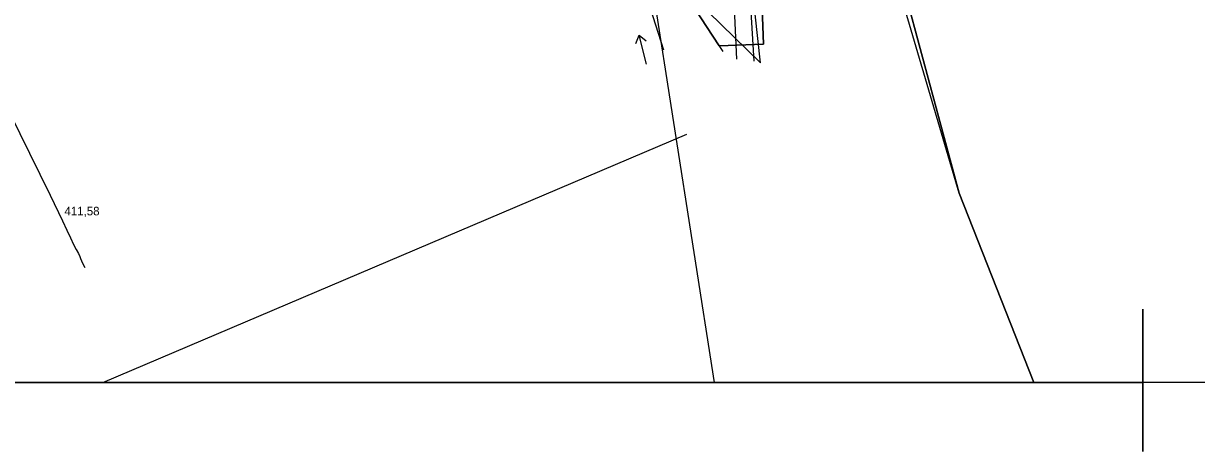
# Model space of a CAD drawing. Extents: x -574342 to -508101, y -1143544 to -1123894.
# Drawn here: x -508449.7 to -508312.9, y -1143544.1 to -1143494.2 of the extents above; entities that cross this region are included whole.
import ezdxf

# ---------------------------------------------------------------- set-up
doc = ezdxf.new("R2010")
doc.units = 0
for name, color, linetype in [('01_PARCELY_NAVRH_PC', 7, 'Continuous'), ('01_PARCELY_NAVRH_ZPF', 7, 'Continuous'), ('01_PARCELY_NAVRH_ŽP', 7, 'Continuous'), ('05_VHO_V_TOK_STAV', 7, 'Continuous'), ('37', 7, 'Continuous'), ('42', 7, 'Continuous'), ('43', 7, 'Continuous'), ('55', 7, 'Continuous'), ('60', 7, 'Continuous'), ('Level 1', 7, 'Continuous'), ('Level 255', 7, 'Continuous'), ('VRST VEDL', 7, 'Continuous')]:
    doc.layers.add(name, color=color, linetype=linetype)

msp = doc.modelspace()

# ---------------------------------------------------------------- linework, layer by layer
msp.add_lwpolyline([(-508319.1, -1143527.49), (-508319.1, -1143527.49), (-508319.1, -1143544.11), (-508319.1, -1143544.11)], close=True)
msp.add_lwpolyline([(-508319.1, -1143527.49), (-508319.1, -1143527.49), (-508319.1, -1143544.11), (-508319.1, -1143544.11)], close=True)
msp.add_lwpolyline([(-508319.1, -1143527.49), (-508319.1, -1143527.49), (-508319.1, -1143544.11), (-508319.1, -1143544.11)], close=True)
msp.add_lwpolyline([(-508319.1, -1143527.49), (-508319.1, -1143527.49), (-508319.1, -1143544.11), (-508319.1, -1143544.11)], close=True)
msp.add_lwpolyline([(-508319.1, -1143527.49), (-508319.1, -1143527.49), (-508319.1, -1143544.11), (-508319.1, -1143544.11)], close=True)
msp.add_lwpolyline([(-508319.1, -1143527.49), (-508319.1, -1143527.49), (-508319.1, -1143544.11), (-508319.1, -1143544.11)], close=True)
msp.add_lwpolyline([(-508319.1, -1143527.49), (-508319.1, -1143527.49), (-508319.1, -1143544.11), (-508319.1, -1143544.11)], close=True)
msp.add_lwpolyline([(-508319.1, -1143527.49), (-508319.1, -1143527.49), (-508319.1, -1143544.11), (-508319.1, -1143544.11)], close=True)
msp.add_lwpolyline([(-508319.1, -1143527.49), (-508319.1, -1143527.49), (-508319.1, -1143544.11), (-508319.1, -1143544.11)], close=True)
msp.add_lwpolyline([(-508319.1, -1143527.49), (-508319.1, -1143527.49), (-508319.1, -1143544.11), (-508319.1, -1143544.11)], close=True)
msp.add_lwpolyline([(-508319.1, -1143527.49), (-508319.1, -1143527.49), (-508319.1, -1143544.11), (-508319.1, -1143544.11)], close=True)
msp.add_lwpolyline([(-508319.1, -1143527.49), (-508319.1, -1143527.49), (-508319.1, -1143544.11), (-508319.1, -1143544.11)], close=True)
msp.add_lwpolyline([(-508319.1, -1143527.49), (-508319.1, -1143527.49), (-508319.1, -1143544.11), (-508319.1, -1143544.11)], close=True)
msp.add_lwpolyline([(-508319.1, -1143527.49), (-508319.1, -1143527.49), (-508319.1, -1143544.11), (-508319.1, -1143544.11)], close=True)
msp.add_lwpolyline([(-508319.1, -1143527.49), (-508319.1, -1143527.49), (-508319.1, -1143544.11), (-508319.1, -1143544.11)], close=True)
at = {"layer": '01_PARCELY_NAVRH_PC'}
msp.add_lwpolyline([(-508332.96, -1143441.42), (-508338.77, -1143439.04), (-508349.31, -1143439.84), (-508360.62, -1143444.62), (-508364.09, -1143448.52), (-508366.9, -1143457.4), (-508369.07, -1143476.28), (-508375.66, -1143485.8), (-508368.53, -1143496.78), (-508363.35, -1143496.57), (-508364.08, -1143476.62), (-508363.77, -1143471.67), (-508362.84, -1143461.25), (-508358.61, -1143451.78), (-508349.41, -1143446.37), (-508339.29, -1143444.12)], close=True, dxfattribs=at)
at = {"layer": '01_PARCELY_NAVRH_ZPF'}
for points in [[(-508319.1, -1143454.32), (-508332.96, -1143441.42), (-508339.29, -1143444.12), (-508349.41, -1143446.37), (-508358.61, -1143451.78), (-508355.5, -1143458.4), (-508340.54, -1143513.97), (-508331.83, -1143536.06)], [(-508331.83, -1143536.06), (-508319.1, -1143536.06)]]:
    msp.add_lwpolyline(points, dxfattribs=at)
at = {"layer": '01_PARCELY_NAVRH_ŽP'}
msp.add_line((-508488.49, -1143536.06), (-508331.83, -1143536.06), dxfattribs=at)
msp.add_lwpolyline([(-508331.83, -1143536.06), (-508340.54, -1143513.97), (-508355.5, -1143458.4), (-508358.61, -1143451.78), (-508362.84, -1143461.25), (-508363.77, -1143471.67), (-508364.08, -1143476.62), (-508363.35, -1143496.57), (-508368.53, -1143496.78), (-508375.66, -1143485.8), (-508391.38, -1143484.87), (-508409.7, -1143432.51), (-508425.23, -1143400.39), (-508448.26, -1143343.08)], dxfattribs=at)
at = {"layer": '05_VHO_V_TOK_STAV'}
for points in [[(-508369.06, -1143536.06), (-508378.54, -1143475.37), (-508396.74, -1143399.68), (-508414.31, -1143332.66)], [(-508440.39, -1143536.06), (-508372.3, -1143507.1)]]:
    msp.add_lwpolyline(points, dxfattribs=at)
at = {"layer": '37'}
msp.add_lwpolyline([(-508374.96, -1143497.27), (-508378.04, -1143487.63), (-508379.64, -1143474.59)], dxfattribs=at)
msp.add_lwpolyline([(-508374.96, -1143497.27), (-508378.04, -1143487.63), (-508379.64, -1143474.59)], dxfattribs=at)
at = {"layer": '42'}
for points in [[(-508369.8, -1143492.82), (-508363.69, -1143498.77), (-508365.82, -1143479.55), (-508363.35, -1143463.84), (-508361.14, -1143456.92), (-508355.5, -1143458.4)], [(-508369.8, -1143492.82), (-508363.69, -1143498.77), (-508365.82, -1143479.55), (-508363.35, -1143463.84), (-508361.14, -1143456.92), (-508355.5, -1143458.4)], [(-508331.83, -1143536.06), (-508340.54, -1143513.97), (-508347.41, -1143490.57), (-508352.38, -1143470.38), (-508355.5, -1143458.4)], [(-508331.83, -1143536.06), (-508340.54, -1143513.97), (-508347.41, -1143490.57), (-508352.38, -1143470.38), (-508355.5, -1143458.4)]]:
    msp.add_lwpolyline(points, dxfattribs=at)
at = {"layer": '43'}
for p, q in [((-508378.24, -1143496.51), (-508377.84, -1143495.52)), ((-508376.99, -1143498.92), (-508377.84, -1143495.52)), ((-508377.84, -1143495.52), (-508377.03, -1143496.21))]:
    msp.add_line(p, q, dxfattribs=at)
at = {"layer": '55'}
for points in [[(-508337.06, -1143438.28), (-508338.45, -1143439.21), (-508345.88, -1143441.87), (-508354.25, -1143443.55), (-508359.29, -1143446.67), (-508363.7, -1143452.22), (-508366.26, -1143459.6), (-508367.57, -1143475.5), (-508366.52, -1143498.33)], [(-508337.06, -1143438.28), (-508338.45, -1143439.21), (-508345.88, -1143441.87), (-508354.25, -1143443.55), (-508359.29, -1143446.67), (-508363.7, -1143452.22), (-508366.26, -1143459.6), (-508367.57, -1143475.5), (-508366.52, -1143498.33)], [(-508364.46, -1143498.56), (-508365.86, -1143475.44), (-508364.17, -1143460.34), (-508362.01, -1143453.3), (-508357.87, -1143448.34), (-508353.24, -1143445.67), (-508345.29, -1143444.08), (-508339.86, -1143444.48), (-508336.23, -1143446.55)], [(-508364.46, -1143498.56), (-508365.86, -1143475.44), (-508364.17, -1143460.34), (-508362.01, -1143453.3), (-508357.87, -1143448.34), (-508353.24, -1143445.67), (-508345.29, -1143444.08), (-508339.86, -1143444.48), (-508336.23, -1143446.55)]]:
    msp.add_lwpolyline(points, dxfattribs=at)
at = {"layer": '60'}
msp.add_lwpolyline([(-508338.69, -1143438.96), (-508348.76, -1143439.73), (-508360.27, -1143444.31), (-508364.03, -1143448.37), (-508366.9, -1143457.4), (-508368.06, -1143463.98), (-508369.07, -1143476.28), (-508375.66, -1143485.8), (-508368.09, -1143497.46)], dxfattribs=at)
msp.add_lwpolyline([(-508338.69, -1143438.96), (-508348.76, -1143439.73), (-508360.27, -1143444.31), (-508364.03, -1143448.37), (-508366.9, -1143457.4), (-508368.06, -1143463.98), (-508369.07, -1143476.28), (-508375.66, -1143485.8), (-508368.09, -1143497.46)], dxfattribs=at)
at = {"layer": 'Level 1'}
msp.add_lwpolyline([(-508703.1, -1143116.06), (-508109.1, -1143116.06), (-508109.1, -1143536.06), (-508703.1, -1143536.06)], close=True, dxfattribs=at)
at = {"layer": 'VRST VEDL'}
msp.add_lwpolyline([(-508452.29, -1143502.49), (-508448.95, -1143509.3), (-508446.56, -1143514.19), (-508445.12, -1143517.18), (-508444.62, -1143518.27), (-508444.19, -1143519.18), (-508443.81, -1143519.94), (-508443.5, -1143520.53), (-508443.26, -1143521), (-508443.1, -1143521.36), (-508443.01, -1143521.6), (-508442.91, -1143521.85), (-508442.79, -1143522.12), (-508442.52, -1143522.65)], dxfattribs=at)

# ---------------------------------------------------------------- texts
at = {"layer": 'Level 255'}
msp.add_text('411,58', height=1, dxfattribs=at).set_placement((-508444.88, -1143516.56))

doc.saveas('drawing.dxf')
